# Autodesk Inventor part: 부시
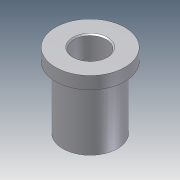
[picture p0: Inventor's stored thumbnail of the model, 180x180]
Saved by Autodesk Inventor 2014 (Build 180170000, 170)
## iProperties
Company: 한국ATC센터
Created: 2014-01
Part Number: 부시
Document SubType Name: Modeling
Designer: KYOUNG IL JANG
Density: 7.85 g/cm^3
Material: 강철
Mass: 67.4287 g
Surface Area: 43.3569 cm^2
Volume: 8.58964 cm^3
Vendor: CBT Solutions
Appearance: 강철
Author: KYOUNG IL JANG
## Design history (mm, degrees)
sketch "스케치1"
  geometry: C1 r 11 at (0, 0) reference; C2 r 14 at (0, 0) reference; C3 r 11 at (0, 0) reference; 1 further point
  node "참조1"
  node "참조2"
extrude "돌출1" new body sketch "스케치1" distance "d0" = 5; taper "d1" = 0 deg
extrude "돌출2" join sketch "스케치1" distance "d2" = 25; taper "d3" = 0 deg
hole "구멍1" diameter "d6" = 13; stored, may be unused: countersink angle "d10" = 90 deg, drill point angle "d12" = 118 deg; dims "d4" = 10, "d5" = 10, "d7" = 6, "d8" = 4, "d9" = 2, "d11" = 8
chamfer "모따기1" distance "d13" = 0.5; stored, may be unused: second distance "d14" = 2, angle "d15" = 45 deg
node "솔리드1"
